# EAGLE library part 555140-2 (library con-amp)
AMP connector
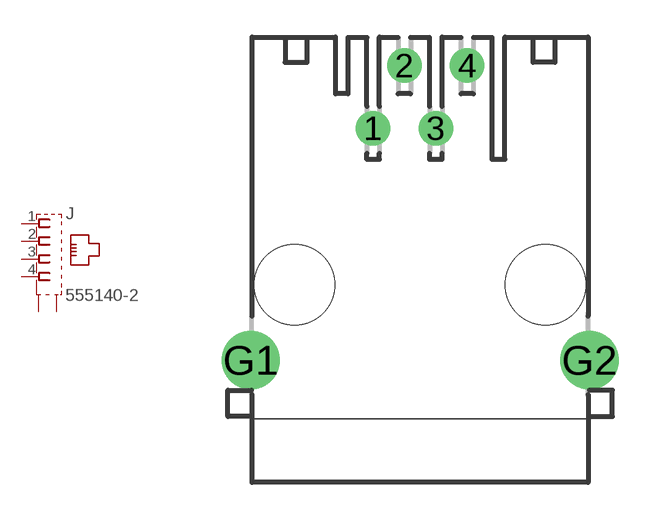
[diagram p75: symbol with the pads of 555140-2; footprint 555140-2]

Designator prefix J

## 555140-2 (MF: TYCO ELECTRONICS; MPN: 5555140-2; OC_FARNELL: 1764707; OC_NEWARK: 42K8748)  [555140-2]
1  1  pas
2  2  pas
3  3  pas
4  4  pas
G1  S1  pas
G2  S2  pas

## Footprint 555140-2 (pad centres in mm)
Modular Jack PC Board Ground
drill 0.889 round: 1 -1.905,6.35; 2 -0.635,8.89; 3 0.635,6.35; 4 1.905,8.89
drill 1.575 pad 2.184 round: G1 -6.858,-3.048; G2 6.858,-3.048
hole 3.251 at -5.08,0
hole 3.251 at 5.08,0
